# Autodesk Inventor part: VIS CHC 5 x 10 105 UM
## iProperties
Shininess: 20.0
Angle Display Precision: 2
Document Length Units: 11269
Document Angle Units: 11279
Document Time Units: 11290
Document Mass Units: 11283
Document Length Units Precision: 3
Document Angle Units Precision: 2
Created: 2002-02
Part Number: VIS CHC 5 x 10 105 UM
Material: Par défaut
Catalog Web Link: www.traceparts.com
Description: Vis tête cylindrique a 6 pans creux
Vendor: RABOURDIN
Document SubType Name: Modélisation
Standard: 527 - 5 x 10
Designer: Administrateur
Density: 0.0
Volumn: 0.0
Area: 0.0
PropertySet Name: Model Information
Control State: 0
Master: False
Checked Out: False
Author: Administrateur
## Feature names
1. Base1
